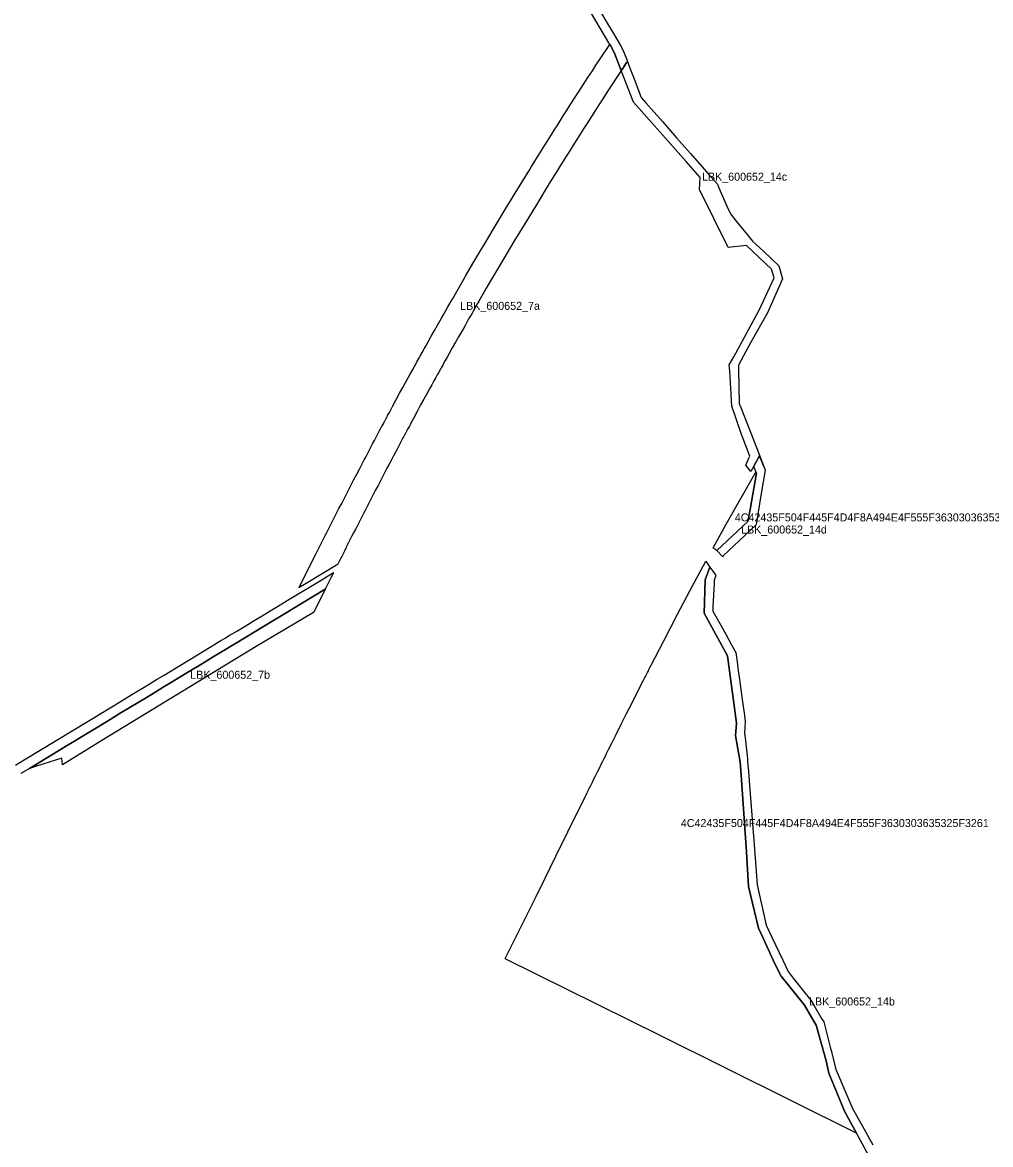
# Model space of a CAD drawing. Extents: x -537012 to -534434, y -1176840 to -1172739.
# Drawn here: x -536126 to -535522, y -1174115 to -1173414 of the extents above; entities that cross this region are included whole.
import ezdxf

# ---------------------------------------------------------------- set-up
doc = ezdxf.new("R2010")
doc.units = 0
for name, color, linetype in [('91270023', 7, 'Continuous'), ('91280013', 7, 'Continuous'), ('91280023', 7, 'Continuous')]:
    doc.layers.add(name, color=color, linetype=linetype)

msp = doc.modelspace()

# ---------------------------------------------------------------- linework, layer by layer
at = {"layer": '91270023'}
for points in [[(-535692.64, -1173743.73), (-535694.65, -1173742.49), (-535695.05, -1173742.16), (-535686.92, -1173727.29), (-535668.99, -1173695.85), (-535668.29, -1173694.6), (-535667.97, -1173695.42), (-535671.95, -1173718.08), (-535673.33, -1173725.68)], [(-535605.58, -1174107.71), (-535728.12, -1174046.76), (-535824.34, -1173998.89), (-535824.79, -1173998.66), (-535818.37, -1173985.73), (-535805.55, -1173959.78), (-535799.96, -1173948.44), (-535793.19, -1173934.7), (-535785.64, -1173919.36), (-535774.94, -1173897.65), (-535774.54, -1173896.85), (-535774.14, -1173896.05), (-535773.75, -1173895.25), (-535773.35, -1173894.45), (-535772.96, -1173893.65), (-535772.56, -1173892.85), (-535772.17, -1173892.05), (-535771.77, -1173891.25), (-535771.37, -1173890.45), (-535770.98, -1173889.65), (-535770.19, -1173888.05), (-535769.4, -1173886.45), (-535768.61, -1173884.85), (-535767.81, -1173883.25), (-535767.02, -1173881.66), (-535765.84, -1173879.26), (-535765.05, -1173877.67), (-535763.86, -1173875.28), (-535763.07, -1173873.69), (-535762.28, -1173872.1), (-535761.49, -1173870.5), (-535760.3, -1173868.12), (-535758.32, -1173864.15), (-535755.55, -1173858.6), (-535752.16, -1173851.81), (-535749.21, -1173845.94), (-535746.04, -1173839.64), (-535739.67, -1173827.06), (-535739.27, -1173826.28), (-535738.88, -1173825.5), (-535738.48, -1173824.72), (-535738.08, -1173823.93), (-535737.68, -1173823.15), (-535737.28, -1173822.37), (-535736.48, -1173820.8), (-535736.08, -1173820.02), (-535735.68, -1173819.24), (-535734.89, -1173817.68), (-535734.49, -1173816.9), (-535734.09, -1173816.12), (-535733.69, -1173815.34), (-535726.08, -1173800.55), (-535717.2, -1173783.55), (-535709.48, -1173768.95), (-535699.59, -1173750.49), (-535697.05, -1173754.05), (-535700.01, -1173762), (-535700.71, -1173782.81), (-535686.02, -1173809.63), (-535680.41, -1173851.56), (-535681.01, -1173859.2), (-535678.16, -1173875.97), (-535677.62, -1173884.09), (-535674.12, -1173932.13), (-535672.91, -1173953.63), (-535666.8, -1173979.63), (-535663.65, -1173986.37), (-535656.49, -1174001.97), (-535652.66, -1174009.5), (-535638.06, -1174027.71), (-535630.74, -1174040.13), (-535624.39, -1174062.44), (-535622.88, -1174070.09), (-535612.99, -1174094.02)]]:
    msp.add_lwpolyline(points, close=True, dxfattribs=at)
at = {"layer": '91280013'}
msp.add_lwpolyline([(-536130.48, -1173877.8), (-536124.97, -1173874.53), (-536085, -1173850.27), (-536082.06, -1173848.49), (-536071.44, -1173842.04), (-536068.28, -1173840.12), (-536057.75, -1173833.73), (-536047.04, -1173827.23), (-536042.37, -1173824.39), (-536037.66, -1173821.53), (-536027.51, -1173815.37), (-536016.81, -1173808.87), (-536012.05, -1173805.98), (-536007.72, -1173803.35), (-536002.27, -1173800.04), (-536000.01, -1173798.67), (-535997.13, -1173796.93), (-535991.99, -1173793.82), (-535987.18, -1173790.91), (-535981.54, -1173787.5), (-535976.5, -1173784.46), (-535971.51, -1173781.44), (-535967.03, -1173778.73), (-535960.88, -1173775.01), (-535939.75, -1173762.23), (-535931.97, -1173757.52), (-535932.12, -1173757.82), (-535932.63, -1173758.85), (-535933.45, -1173760.49), (-535934.27, -1173762.12), (-535935.09, -1173763.76), (-535935.91, -1173765.39), (-535936.73, -1173767.03), (-535937.15, -1173767.87), (-535945.08, -1173772.67), (-535952.93, -1173777.42), (-535961.54, -1173782.63), (-535965.74, -1173785.17), (-535969.79, -1173787.62), (-535993.13, -1173801.73), (-535996.73, -1173803.91), (-535998.32, -1173804.88), (-536003.86, -1173808.25), (-536008.07, -1173810.8), (-536012.78, -1173813.66), (-536023.5, -1173820.17), (-536033.67, -1173826.35), (-536038.31, -1173829.17), (-536042.95, -1173831.99), (-536048.32, -1173835.25), (-536065.07, -1173845.42), (-536073.11, -1173850.3), (-536080.97, -1173855.07), (-536089.33, -1173860.15), (-536093.61, -1173862.75), (-536097.5, -1173865.11), (-536121.73, -1173879.82), (-536127.22, -1173883.05)], dxfattribs=at)
at = {"layer": '91280023'}
for points in [[(-535765.58, -1173406.86), (-535761.14, -1173414.39), (-535757.31, -1173420.88), (-535752.87, -1173428.42), (-535751.35, -1173430.99), (-535749.58, -1173435.6), (-535748.57, -1173438.22), (-535749.05, -1173438.92), (-535749.18, -1173439.12), (-535749.4, -1173439.46), (-535749.69, -1173439.9), (-535750.38, -1173440.96), (-535751.46, -1173442.6), (-535752.34, -1173443.92), (-535756.52, -1173433.09), (-535759.12, -1173428.42), (-535759.55, -1173427.69), (-535774.26, -1173402.73)], [(-535597.91, -1174121.88), (-535603.1, -1174112.3), (-535605.58, -1174107.71), (-535612.99, -1174094.02), (-535622.88, -1174070.09), (-535624.39, -1174062.44), (-535630.74, -1174040.13), (-535638.06, -1174027.71), (-535652.66, -1174009.5), (-535656.49, -1174001.97), (-535663.65, -1173986.37), (-535666.8, -1173979.63), (-535672.91, -1173953.63), (-535674.12, -1173932.13), (-535677.62, -1173884.09), (-535678.16, -1173875.97), (-535681.01, -1173859.2), (-535680.41, -1173851.56), (-535686.02, -1173809.63), (-535700.71, -1173782.81), (-535700.01, -1173762), (-535697.05, -1173754.05), (-535693.54, -1173758.96), (-535693.31, -1173759.31), (-535694.35, -1173762.25), (-535694.45, -1173764.25), (-535695.15, -1173778.81), (-535695.28, -1173781.53), (-535690.11, -1173790.84), (-535686.98, -1173796.48), (-535683.59, -1173802.59), (-535680.9, -1173807.44), (-535680.09, -1173813.33), (-535679.35, -1173818.68), (-535678.57, -1173824.37), (-535676.87, -1173836.7), (-535675.47, -1173846.86), (-535674.97, -1173850.53), (-535675.37, -1173858.05), (-535675.08, -1173860.72), (-535673.63, -1173873.95), (-535673.58, -1173874.6), (-535673.49, -1173875.79), (-535673.04, -1173881.63), (-535672.35, -1173890.56), (-535672.17, -1173892.95), (-535669.5, -1173927.55), (-535667.57, -1173952.61), (-535661.87, -1173977.65), (-535658.36, -1173985.16), (-535651.57, -1173999.71), (-535648.27, -1174006.76), (-535645.01, -1174010.83), (-535637.75, -1174019.91), (-535633.96, -1174024.65), (-535632.16, -1174027.72), (-535627.31, -1174035.98), (-535626.01, -1174038.2), (-535623.68, -1174047.25), (-535621.96, -1174053.94), (-535621.02, -1174057.59), (-535620.15, -1174060.99), (-535618.79, -1174066.25), (-535618.25, -1174068.37), (-535617.67, -1174069.74), (-535616.27, -1174073.01), (-535613.52, -1174079.48), (-535608.47, -1174091.3), (-535608.17, -1174091.85), (-535601.9, -1174103.21), (-535595.39, -1174115.02)]]:
    msp.add_lwpolyline(points, dxfattribs=at)
for points in [[(-535759.55, -1173427.69), (-535759.12, -1173428.42), (-535756.52, -1173433.09), (-535752.34, -1173443.92), (-535753.05, -1173444.98), (-535755.58, -1173448.83), (-535757.85, -1173452.35), (-535760.66, -1173456.57), (-535763.47, -1173460.97), (-535766.37, -1173465.46), (-535767.41, -1173467.11), (-535768.51, -1173468.76), (-535769.29, -1173469.99), (-535770.58, -1173471.97), (-535771.12, -1173472.81), (-535772.4, -1173474.86), (-535773.9, -1173477.22), (-535775.95, -1173480.36), (-535779.1, -1173485.35), (-535780.2, -1173487.12), (-535781.54, -1173489.23), (-535783.04, -1173491.61), (-535784.97, -1173494.7), (-535787.04, -1173497.94), (-535788.7, -1173500.63), (-535790.41, -1173503.44), (-535792.64, -1173506.93), (-535794.26, -1173509.57), (-535795.59, -1173511.7), (-535796.72, -1173513.55), (-535805.78, -1173528.45), (-535812.02, -1173538.6), (-535819.48, -1173550.82), (-535823.51, -1173557.91), (-535828.4, -1173565.98), (-535832.07, -1173572.1), (-535836.59, -1173579.98), (-535838.73, -1173583.65), (-535842.03, -1173589.46), (-535844.79, -1173594.23), (-535845.5, -1173595.47), (-535847.04, -1173598.17), (-535847.65, -1173599.15), (-535848.69, -1173601.04), (-535850.1, -1173603.55), (-535851.56, -1173606.18), (-535854.01, -1173610.34), (-535855.84, -1173613.7), (-535857.86, -1173617.18), (-535859.76, -1173620.67), (-535861.04, -1173622.93), (-535862.2, -1173625.07), (-535863.5, -1173627.33), (-535863.82, -1173627.94), (-535864.19, -1173628.6), (-535864.82, -1173629.72), (-535865.29, -1173630.57), (-535866.5, -1173632.73), (-535867.21, -1173634.07), (-535868.07, -1173635.6), (-535869.29, -1173637.83), (-535870.7, -1173640.37), (-535872.01, -1173642.75), (-535874.03, -1173646.36), (-535875.5, -1173649.17), (-535877.58, -1173652.84), (-535879.78, -1173656.88), (-535881.86, -1173660.91), (-535883.86, -1173664.58), (-535884.21, -1173665.24), (-535884.64, -1173666.01), (-535884.96, -1173666.61), (-535885.31, -1173667.27), (-535885.72, -1173668.05), (-535886.31, -1173669.14), (-535886.46, -1173669.43), (-535886.68, -1173669.83), (-535886.84, -1173670.13), (-535887.04, -1173670.5), (-535887.21, -1173670.83), (-535887.43, -1173671.24), (-535887.71, -1173671.75), (-535887.91, -1173672.13), (-535888.16, -1173672.6), (-535888.55, -1173673.33), (-535888.56, -1173673.34), (-535888.56, -1173673.35), (-535888.57, -1173673.37), (-535888.58, -1173673.38), (-535888.58, -1173673.39), (-535888.58, -1173673.4), (-535888.59, -1173673.4), (-535888.59, -1173673.41), (-535888.6, -1173673.43), (-535888.61, -1173673.44), (-535888.62, -1173673.46), (-535889.92, -1173675.92), (-535891.24, -1173678.38), (-535892.54, -1173680.85), (-535894.28, -1173684.14), (-535895.58, -1173686.61), (-535897.31, -1173689.9), (-535898.61, -1173692.37), (-535899.47, -1173694.01), (-535901.19, -1173697.3), (-535902.48, -1173699.77), (-535904.19, -1173703.06), (-535905.89, -1173706.34), (-535907.17, -1173708.81), (-535908.02, -1173710.45), (-535908.87, -1173712.1), (-535909.72, -1173713.74), (-535910.56, -1173715.38), (-535911.41, -1173717.03), (-535912.25, -1173718.67), (-535913.1, -1173720.31), (-535913.94, -1173721.96), (-535915.2, -1173724.42), (-535916.04, -1173726.06), (-535916.88, -1173727.7), (-535918.13, -1173730.16), (-535919.39, -1173732.63), (-535920.64, -1173735.09), (-535921.47, -1173736.73), (-535922.72, -1173739.19), (-535923.14, -1173740.01), (-535923.55, -1173740.83), (-535923.97, -1173741.65), (-535924.38, -1173742.47), (-535924.8, -1173743.29), (-535925.21, -1173744.11), (-535925.62, -1173744.93), (-535926.04, -1173745.75), (-535926.45, -1173746.57), (-535926.87, -1173747.39), (-535927.28, -1173748.2), (-535927.69, -1173749.02), (-535928.1, -1173749.84), (-535928.52, -1173750.66), (-535928.93, -1173751.48), (-535929.34, -1173752.3), (-535929.43, -1173752.48), (-535930.06, -1173752.86), (-535948.96, -1173764.29), (-535953.57, -1173767.08), (-535942.74, -1173745.56), (-535942.33, -1173744.74), (-535941.91, -1173743.91), (-535941.5, -1173743.09), (-535941.09, -1173742.27), (-535940.67, -1173741.45), (-535940.26, -1173740.63), (-535939.84, -1173739.81), (-535939.43, -1173738.98), (-535939.01, -1173738.16), (-535938.6, -1173737.34), (-535938.18, -1173736.52), (-535937.77, -1173735.7), (-535937.35, -1173734.87), (-535936.93, -1173734.05), (-535936.52, -1173733.23), (-535936.1, -1173732.41), (-535934.85, -1173729.94), (-535934.01, -1173728.29), (-535932.76, -1173725.82), (-535931.5, -1173723.35), (-535930.24, -1173720.88), (-535929.4, -1173719.23), (-535928.55, -1173717.59), (-535927.29, -1173715.11), (-535926.44, -1173713.47), (-535925.6, -1173711.82), (-535924.75, -1173710.17), (-535923.9, -1173708.52), (-535923.05, -1173706.87), (-535922.2, -1173705.22), (-535921.35, -1173703.57), (-535920.49, -1173701.92), (-535919.21, -1173699.44), (-535917.5, -1173696.14), (-535915.78, -1173692.84), (-535914.49, -1173690.36), (-535912.76, -1173687.06), (-535911.89, -1173685.4), (-535910.59, -1173682.92), (-535908.86, -1173679.62), (-535907.55, -1173677.14), (-535906.46, -1173675.09), (-535904.02, -1173670.46), (-535903.17, -1173668.87), (-535901.95, -1173666.59), (-535901.85, -1173666.38), (-535900.65, -1173664.14), (-535900.43, -1173663.74), (-535900.25, -1173663.39), (-535900.07, -1173663.07), (-535899.92, -1173662.79), (-535899.7, -1173662.38), (-535899.55, -1173662.09), (-535898.96, -1173660.98), (-535898.55, -1173660.22), (-535898.18, -1173659.52), (-535897.82, -1173658.85), (-535897.4, -1173658.09), (-535897.06, -1173657.45), (-535895.11, -1173653.88), (-535893.03, -1173649.85), (-535890.69, -1173645.55), (-535888.68, -1173642), (-535887.23, -1173639.23), (-535885.13, -1173635.47), (-535883.83, -1173633.11), (-535882.43, -1173630.59), (-535881.19, -1173628.33), (-535880.38, -1173626.87), (-535879.66, -1173625.53), (-535878.39, -1173623.27), (-535877.92, -1173622.41), (-535877.28, -1173621.27), (-535877.01, -1173620.8), (-535876.65, -1173620.11), (-535875.3, -1173617.76), (-535874.16, -1173615.65), (-535872.87, -1173613.38), (-535870.94, -1173609.84), (-535868.92, -1173606.35), (-535867.06, -1173602.94), (-535864.58, -1173598.72), (-535863.19, -1173596.23), (-535861.81, -1173593.77), (-535860.6, -1173591.56), (-535859.92, -1173590.48), (-535858.52, -1173588.01), (-535857.79, -1173586.75), (-535855.05, -1173582), (-535851.73, -1173576.17), (-535849.58, -1173572.47), (-535845.01, -1173564.51), (-535841.25, -1173558.24), (-535836.45, -1173550.32), (-535832.4, -1173543.21), (-535824.81, -1173530.76), (-535818.58, -1173520.62), (-535809.53, -1173505.74), (-535808.34, -1173503.8), (-535807.01, -1173501.67), (-535805.35, -1173498.96), (-535803.13, -1173495.5), (-535801.49, -1173492.81), (-535799.75, -1173489.97), (-535797.64, -1173486.68), (-535795.75, -1173483.65), (-535794.22, -1173481.21), (-535792.89, -1173479.13), (-535791.81, -1173477.39), (-535788.58, -1173472.27), (-535786.52, -1173469.1), (-535785.09, -1173466.85), (-535783.78, -1173464.76), (-535783.18, -1173463.84), (-535781.92, -1173461.89), (-535781.08, -1173460.57), (-535780, -1173458.96), (-535779.02, -1173457.4), (-535776.09, -1173452.86), (-535773.22, -1173448.37), (-535770.39, -1173444.13), (-535768.15, -1173440.65), (-535765.55, -1173436.7)], [(-535748.57, -1173438.22), (-535746.8, -1173442.83), (-535744, -1173450.12), (-535740.92, -1173458.17), (-535739.9, -1173460.82), (-535737.04, -1173464.08), (-535726.71, -1173475.86), (-535717.86, -1173485.95), (-535709.19, -1173495.84), (-535697.78, -1173508.85), (-535692.41, -1173514.97), (-535691.44, -1173517.18), (-535686.26, -1173529.03), (-535684.28, -1173533.55), (-535680.66, -1173537.97), (-535673.84, -1173546.31), (-535670.41, -1173550.5), (-535663.43, -1173557.09), (-535654.08, -1173565.9), (-535651.65, -1173574.09), (-535661.19, -1173595.23), (-535671.63, -1173614.14), (-535677.56, -1173624.89), (-535679.29, -1173628.03), (-535679.23, -1173630.64), (-535678.7, -1173651.88), (-535677.33, -1173655.42), (-535668, -1173679.5), (-535663.42, -1173691.33), (-535666.09, -1173684.66), (-535668.4, -1173688.75), (-535669.68, -1173691), (-535671.6, -1173694.36), (-535674.68, -1173690.42), (-535672.65, -1173686.12), (-535672.1, -1173684.83), (-535677.54, -1173670.61), (-535683.41, -1173653.53), (-535684.54, -1173631.55), (-535685.07, -1173627.77), (-535682.21, -1173622.82), (-535666.13, -1173593.26), (-535657.03, -1173573.52), (-535658.57, -1173568.09), (-535674.26, -1173553.24), (-535685.71, -1173554.4), (-535703.6, -1173518.27), (-535703.03, -1173510.68), (-535711.9, -1173500.73), (-535744.67, -1173463.76), (-535752.34, -1173443.92), (-535751.46, -1173442.6), (-535750.38, -1173440.96), (-535749.69, -1173439.9), (-535749.4, -1173439.46), (-535749.18, -1173439.12), (-535749.05, -1173438.92)], [(-535692.64, -1173743.73), (-535673.33, -1173725.68), (-535671.95, -1173718.08), (-535667.97, -1173695.42), (-535668.29, -1173694.6), (-535669.68, -1173691), (-535668.4, -1173688.75), (-535666.09, -1173684.66), (-535663.42, -1173691.33), (-535662.56, -1173693.55), (-535664.98, -1173708.05), (-535668.03, -1173726.35), (-535668.3, -1173727.97), (-535688.76, -1173747.02), (-535689.01, -1173747.62)], [(-535937.15, -1173767.87), (-535937.25, -1173768.07), (-535937.55, -1173768.66), (-535942.03, -1173777.65), (-535944.47, -1173782.56), (-535980.23, -1173803.73), (-536076.51, -1173862.38), (-536101.12, -1173877.67), (-536101.58, -1173873.52), (-536117.44, -1173878.48), (-536121.73, -1173879.82), (-536097.5, -1173865.11), (-536093.61, -1173862.75), (-536089.33, -1173860.15), (-536080.97, -1173855.07), (-536073.11, -1173850.3), (-536065.07, -1173845.42), (-536048.32, -1173835.25), (-536042.95, -1173831.99), (-536038.31, -1173829.17), (-536033.67, -1173826.35), (-536023.5, -1173820.17), (-536012.78, -1173813.66), (-536008.07, -1173810.8), (-536003.86, -1173808.25), (-535998.32, -1173804.88), (-535996.73, -1173803.91), (-535993.13, -1173801.73), (-535969.79, -1173787.62), (-535965.74, -1173785.17), (-535961.54, -1173782.63), (-535952.93, -1173777.42), (-535945.08, -1173772.67)]]:
    msp.add_lwpolyline(points, close=True, dxfattribs=at)

# ---------------------------------------------------------------- texts
at = {"layer": '91270023'}
for s, rotation, p in [('4C42435F504F445F4D4F8A494E4F555F3630303635325F3262', 360, (-535681.51, -1173725.56)), ('4C42435F504F445F4D4F8A494E4F555F3630303635325F3261', 0, (-535715.19, -1173916.47))]:
    msp.add_text(s, height=5, rotation=rotation, dxfattribs=at).set_placement(p)
at = {"layer": '91280023'}
for s, rotation, p in [('LBK_600652_14c', 0, (-535702, -1173512.78)), ('LBK_600652_7a', 360, (-535852.95, -1173593.43)), ('LBK_600652_14d', 360, (-535677.6, -1173733.15)), ('LBK_600652_7b', 360, (-536021.4, -1173823.84)), ('LBK_600652_14b', 360, (-535635.16, -1174027.9))]:
    msp.add_text(s, height=5, rotation=rotation, dxfattribs=at).set_placement(p)

doc.saveas('drawing.dxf')
